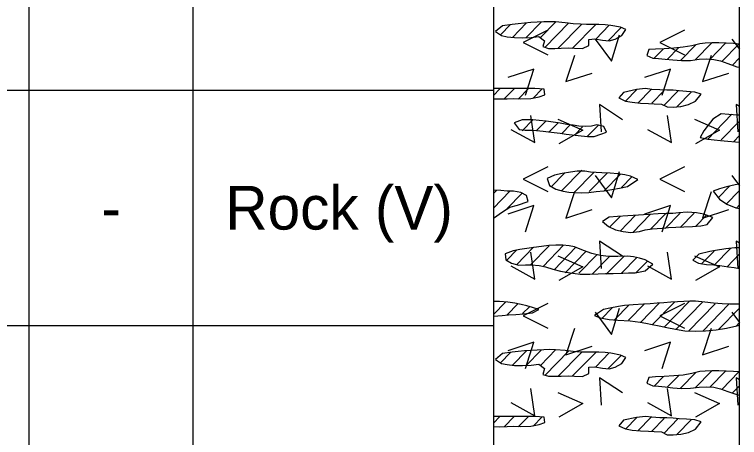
# Model space of a CAD drawing. Extents: x 0 to 0.83, y -0.65 to 1.27.
# Drawn here: x 0.7228 to 0.8333, y 0.0905 to 0.155 of the extents above; entities that cross this region are included whole.
import ezdxf

# ---------------------------------------------------------------- set-up
doc = ezdxf.new("R2010")
doc.units = 0

msp = doc.modelspace()

# ---------------------------------------------------------------- linework, layer by layer
for points in [[(0, 0), (0.83333, 0), (0.83333, 1.275), (0, 1.275)], [(0, 0), (0.83333, 0), (0.83333, 1.275), (0, 1.275)], [(0, 0), (0.83333, 0), (0.83333, 1.275), (0, 1.275)], [(0, 0), (0.83333, 0), (0.83333, 1.275), (0, 1.275)], [(0, 0), (0.83333, 0), (0.83333, 1.275), (0, 1.275)], [(0.79708, 0.15181), (0.79794, 0.15163), (0.79904, 0.15152), (0.80028, 0.15149), (0.80156, 0.15154), (0.80274, 0.1517), (0.80361, 0.15103), (0.80338, 0.15014), (0.80422, 0.14987), (0.80517, 0.14985), (0.80613, 0.1499), (0.8072, 0.14993), (0.80818, 0.1499), (0.80939, 0.14983), (0.81037, 0.1503), (0.81038, 0.15124), (0.8113, 0.15131), (0.81244, 0.15112), (0.81346, 0.15101), (0.81438, 0.15127), (0.81539, 0.15181), (0.81601, 0.15272), (0.81517, 0.1531), (0.81374, 0.15337), (0.81285, 0.15346), (0.81187, 0.15352), (0.81, 0.15352), (0.8091, 0.15354), (0.808, 0.15362), (0.80678, 0.15377), (0.8053, 0.1539), (0.80443, 0.15392), (0.80349, 0.1539), (0.80251, 0.15386), (0.80152, 0.1538), (0.80054, 0.15372), (0.79959, 0.15363), (0.7987, 0.15353), (0.79722, 0.15331), (0.79614, 0.15243)], [(0.83241, 0.15059), (0.83129, 0.15066), (0.83017, 0.15069), (0.8291, 0.1507), (0.82811, 0.15066), (0.82728, 0.15057), (0.82608, 0.15027), (0.82476, 0.15004), (0.8233, 0.14991), (0.82183, 0.14982), (0.82051, 0.14976), (0.81951, 0.14967), (0.81922, 0.1488), (0.82013, 0.14838), (0.82097, 0.14833), (0.822, 0.14823), (0.82318, 0.1481), (0.82448, 0.14801), (0.82584, 0.14804), (0.82719, 0.1482), (0.82836, 0.14827), (0.8294, 0.14819), (0.83043, 0.14795), (0.83156, 0.14756), (0.83291, 0.14707), (0.83333, 0.147), (0.83333, 0.15052)], [(0.79583, 0.14218), (0.79676, 0.14217), (0.79792, 0.14219), (0.79882, 0.14223), (0.79992, 0.14218), (0.80151, 0.14223), (0.80282, 0.14248), (0.80367, 0.1428), (0.80354, 0.14364), (0.80216, 0.14373), (0.79583, 0.14373)], [(0.81822, 0.14153), (0.81944, 0.14148), (0.82033, 0.14143), (0.82145, 0.14137), (0.82229, 0.14095), (0.82324, 0.14091), (0.82438, 0.14101), (0.82555, 0.1413), (0.82662, 0.14181), (0.82749, 0.1429), (0.82651, 0.14321), (0.82524, 0.14331), (0.82413, 0.14337), (0.82324, 0.14348), (0.82226, 0.1435), (0.82121, 0.14352), (0.81995, 0.14361), (0.81902, 0.14373), (0.81761, 0.14359), (0.81566, 0.14314), (0.81496, 0.14231), (0.81598, 0.14182), (0.81695, 0.14164)], [(0.83305, 0.13968), (0.83171, 0.13979), (0.83054, 0.13989), (0.82925, 0.13907), (0.82857, 0.13816), (0.82792, 0.13727), (0.82735, 0.13625), (0.82858, 0.13602), (0.82945, 0.13592), (0.83045, 0.13582), (0.83155, 0.13573), (0.83272, 0.13563), (0.83333, 0.13558), (0.83333, 0.13967)], [(0.80066, 0.13738), (0.80188, 0.13737), (0.80339, 0.13724), (0.80423, 0.13715), (0.8051, 0.13704), (0.806, 0.13692), (0.80692, 0.1368), (0.80784, 0.13668), (0.80875, 0.13657), (0.81014, 0.13643), (0.81119, 0.13644), (0.81222, 0.13678), (0.81308, 0.13707), (0.81267, 0.13797), (0.8116, 0.13822), (0.81075, 0.13802), (0.80989, 0.13794), (0.80885, 0.13802), (0.80799, 0.13813), (0.80703, 0.13827), (0.806, 0.13844), (0.80492, 0.1386), (0.80384, 0.13876), (0.8028, 0.13889), (0.80182, 0.13898), (0.8002, 0.13899), (0.79901, 0.13852), (0.79974, 0.13748)], [(0.81233, 0.13087), (0.81063, 0.13099), (0.80977, 0.13112), (0.8086, 0.13113), (0.80755, 0.13099), (0.80632, 0.13079), (0.80513, 0.13054), (0.80403, 0.13002), (0.80436, 0.12896), (0.80536, 0.1284), (0.80647, 0.1281), (0.8073, 0.12795), (0.80824, 0.12787), (0.80926, 0.12786), (0.81035, 0.12791), (0.81149, 0.12802), (0.81267, 0.12816), (0.81386, 0.12835), (0.81506, 0.12856), (0.81625, 0.12879), (0.81783, 0.12987), (0.81673, 0.13037), (0.81585, 0.13058), (0.8148, 0.13073), (0.81361, 0.13084)], [(0.79583, 0.12396), (0.79719, 0.12495), (0.79831, 0.12565), (0.79951, 0.12593), (0.80111, 0.12653), (0.80086, 0.12741), (0.80002, 0.12789), (0.79889, 0.12808), (0.79791, 0.12811), (0.79694, 0.12817), (0.79583, 0.12825)], [(0.83265, 0.12906), (0.83136, 0.12875), (0.83028, 0.12847), (0.82934, 0.12808), (0.83026, 0.12688), (0.83142, 0.12612), (0.83279, 0.12554), (0.83333, 0.12544), (0.83333, 0.12915)], [(0.82537, 0.12491), (0.82408, 0.12476), (0.82319, 0.1247), (0.82214, 0.12467), (0.82091, 0.12464), (0.81947, 0.12455), (0.81792, 0.12443), (0.81632, 0.12431), (0.81475, 0.12421), (0.81348, 0.12411), (0.81247, 0.12347), (0.81337, 0.12271), (0.81444, 0.12221), (0.81561, 0.12192), (0.81675, 0.12181), (0.81807, 0.12193), (0.81896, 0.1222), (0.82003, 0.12235), (0.82157, 0.12247), (0.82253, 0.12253), (0.82362, 0.12258), (0.82483, 0.12265), (0.82618, 0.12271), (0.82745, 0.12282), (0.82842, 0.123), (0.82927, 0.12405), (0.82791, 0.12457), (0.82679, 0.12477)], [(0.79885, 0.119), (0.79763, 0.11854), (0.79773, 0.11764), (0.79859, 0.11712), (0.7997, 0.11682), (0.80074, 0.11683), (0.80165, 0.11684), (0.80281, 0.11676), (0.80377, 0.11655), (0.80486, 0.1162), (0.80606, 0.11591), (0.80751, 0.11563), (0.80905, 0.11545), (0.81052, 0.11542), (0.81177, 0.11547), (0.81289, 0.11552), (0.81408, 0.11555), (0.81553, 0.11559), (0.81642, 0.11562), (0.81745, 0.11565), (0.81897, 0.11592), (0.82011, 0.11696), (0.81896, 0.11763), (0.8181, 0.11789), (0.81717, 0.11809), (0.81626, 0.1182), (0.81479, 0.11814), (0.81343, 0.11814), (0.8121, 0.11829), (0.8108, 0.11859), (0.80953, 0.11905), (0.8082, 0.1196), (0.80736, 0.11976), (0.8064, 0.11984), (0.80536, 0.11984), (0.80427, 0.11978), (0.80314, 0.11967), (0.80201, 0.11952), (0.8009, 0.11935), (0.79984, 0.11918)], [(0.83263, 0.11944), (0.83126, 0.11931), (0.82969, 0.11904), (0.82883, 0.11887), (0.82712, 0.11846), (0.82623, 0.11759), (0.82708, 0.1171), (0.82831, 0.11691), (0.82941, 0.11684), (0.83033, 0.11675), (0.83165, 0.11657), (0.83253, 0.11643), (0.83333, 0.11629), (0.83333, 0.11944)], [(0.79583, 0.10904), (0.79715, 0.10915), (0.79814, 0.10922), (0.79922, 0.1093), (0.80039, 0.10939), (0.80179, 0.10951), (0.80275, 0.11002), (0.80179, 0.11036), (0.80091, 0.11058), (0.80003, 0.1108), (0.79909, 0.11101), (0.79803, 0.11117), (0.79677, 0.11127), (0.79583, 0.11125)], [(0.82816, 0.10679), (0.82978, 0.10696), (0.83137, 0.10721), (0.8329, 0.10753), (0.83333, 0.10763), (0.83333, 0.11087), (0.83295, 0.11084), (0.83188, 0.11086), (0.83071, 0.11091), (0.82938, 0.11101), (0.82807, 0.11118), (0.82662, 0.1113), (0.82576, 0.1113), (0.82484, 0.11128), (0.82387, 0.11123), (0.82286, 0.11116), (0.82182, 0.11108), (0.82077, 0.11099), (0.81973, 0.11091), (0.81872, 0.11084), (0.81715, 0.11074), (0.81579, 0.11065), (0.81491, 0.11052), (0.81357, 0.11024), (0.8126, 0.11003), (0.81121, 0.10911), (0.8121, 0.10875), (0.81345, 0.1085), (0.81479, 0.10841), (0.81668, 0.10831), (0.81818, 0.10811), (0.81905, 0.10796), (0.82, 0.10778), (0.82107, 0.10757), (0.82225, 0.10732), (0.82357, 0.10703), (0.82501, 0.1068), (0.82656, 0.10673)], [(0.79708, 0.10181), (0.79794, 0.10163), (0.79904, 0.10152), (0.80028, 0.10149), (0.80156, 0.10154), (0.80274, 0.1017), (0.80361, 0.10103), (0.80338, 0.10014), (0.80422, 0.09987), (0.80517, 0.09985), (0.80613, 0.0999), (0.8072, 0.09993), (0.80818, 0.0999), (0.80939, 0.09983), (0.81037, 0.1003), (0.81038, 0.10124), (0.8113, 0.10131), (0.81244, 0.10112), (0.81346, 0.10101), (0.81438, 0.10127), (0.81539, 0.10181), (0.81601, 0.10272), (0.81517, 0.1031), (0.81374, 0.10337), (0.81285, 0.10346), (0.81187, 0.10352), (0.81, 0.10352), (0.8091, 0.10354), (0.808, 0.10362), (0.80678, 0.10377), (0.8053, 0.1039), (0.80443, 0.10392), (0.80349, 0.1039), (0.80251, 0.10386), (0.80152, 0.1038), (0.80054, 0.10372), (0.79959, 0.10363), (0.7987, 0.10353), (0.79722, 0.10331), (0.79614, 0.10243)], [(0.83241, 0.10059), (0.83129, 0.10066), (0.83017, 0.10069), (0.8291, 0.1007), (0.82811, 0.10066), (0.82728, 0.10057), (0.82608, 0.10027), (0.82476, 0.10004), (0.8233, 0.09991), (0.82183, 0.09982), (0.82051, 0.09976), (0.81951, 0.09967), (0.81922, 0.0988), (0.82013, 0.09838), (0.82097, 0.09833), (0.822, 0.09823), (0.82318, 0.0981), (0.82448, 0.09801), (0.82584, 0.09804), (0.82719, 0.0982), (0.82836, 0.09827), (0.8294, 0.09819), (0.83043, 0.09795), (0.83156, 0.09756), (0.83291, 0.09707), (0.83333, 0.097), (0.83333, 0.10052)], [(0.79583, 0.09218), (0.79676, 0.09217), (0.79792, 0.09219), (0.79882, 0.09223), (0.79992, 0.09218), (0.80151, 0.09223), (0.80282, 0.09248), (0.80367, 0.0928), (0.80354, 0.09364), (0.80216, 0.09373), (0.79583, 0.09373)], [(0.81822, 0.09153), (0.81944, 0.09148), (0.82033, 0.09143), (0.82145, 0.09137), (0.82229, 0.09095), (0.82324, 0.09091), (0.82438, 0.09101), (0.82555, 0.0913), (0.82662, 0.09181), (0.82749, 0.0929), (0.82651, 0.09321), (0.82524, 0.09331), (0.82413, 0.09337), (0.82324, 0.09348), (0.82226, 0.0935), (0.82121, 0.09352), (0.81995, 0.09361), (0.81902, 0.09373), (0.81761, 0.09359), (0.81566, 0.09314), (0.81496, 0.09231), (0.81598, 0.09182), (0.81695, 0.09164)]]:
    msp.add_lwpolyline(points, close=True)
for points in [[(0.725, 1.22083), (0.725, -0.64575)], [(0.75, 1.22083), (0.75, -0.64575)], [(0.75, 1.22083), (0.75, -0.64575)], [(0.79583, 1.22083), (0.79583, -0.64575)], [(0.725, 1.20833), (0.725, -0.64575)], [(0.83333, -0.64575), (0.83333, 1.13365)], [(0.79871, 0.15155), (0.80085, 0.15374)], [(0.80083, 0.15151), (0.80311, 0.15385)], [(0.80534, 0.15392), (0.80299, 0.15151)], [(0.80367, 0.15), (0.80732, 0.15374)], [(0.79844, 0.15349), (0.79691, 0.15192)], [(0.80412, 0.15263), (0.80038, 0.15076), (0.80412, 0.14888)], [(0.80571, 0.14988), (0.80924, 0.15349)], [(0.81142, 0.15351), (0.80785, 0.14986)], [(0.81141, 0.15129), (0.81348, 0.15341)], [(0.81528, 0.15305), (0.81331, 0.15103)], [(0.82496, 0.15263), (0.82121, 0.15076), (0.82496, 0.14888)], [(0.81134, 0.15129), (0.81384, 0.14792), (0.81503, 0.15192)], [(0.82433, 0.14802), (0.82666, 0.15041)], [(0.82909, 0.1507), (0.82656, 0.1481)], [(0.82885, 0.14823), (0.83122, 0.15066)], [(0.83325, 0.15052), (0.83065, 0.14786)], [(0.83217, 0.15129), (0.83333, 0.14973)], [(0.82035, 0.14837), (0.82176, 0.14982)], [(0.82233, 0.14819), (0.82408, 0.14998)], [(0.80818, 0.1488), (0.80687, 0.1448), (0.81087, 0.14611)], [(0.82901, 0.1488), (0.8277, 0.1448), (0.8317, 0.14611)], [(0.83333, 0.1484), (0.83227, 0.14731)], [(0.80069, 0.14272), (0.802, 0.14672), (0.798, 0.14541)], [(0.82152, 0.14272), (0.82284, 0.14672), (0.81884, 0.14541)], [(0.79583, 0.1427), (0.79681, 0.1437)], [(0.79898, 0.14372), (0.79747, 0.14217)], [(0.80116, 0.14373), (0.79959, 0.14213)], [(0.80328, 0.14369), (0.80188, 0.14226)], [(0.70417, 0.1435), (0.725, 0.1435)], [(0.725, 0.1435), (0.75, 0.1435)], [(0.75, 0.1435), (0.79583, 0.1435)], [(0.8177, 0.14359), (0.81596, 0.14181)], [(0.81988, 0.14361), (0.81785, 0.14153)], [(0.82185, 0.14342), (0.81997, 0.14149)], [(0.824, 0.14341), (0.82178, 0.14113)], [(0.82601, 0.14325), (0.82378, 0.14097)], [(0.81551, 0.13899), (0.81201, 0.14131), (0.81226, 0.13712)], [(0.83333, 0.14098), (0.83284, 0.14131), (0.83309, 0.13712)], [(0.79847, 0.13751), (0.80215, 0.13551), (0.80153, 0.13964)], [(0.8193, 0.13751), (0.82299, 0.13551), (0.82236, 0.13964)], [(0.83217, 0.13981), (0.82844, 0.13599)], [(0.80188, 0.13903), (0.8002, 0.13731)], [(0.8038, 0.13879), (0.80237, 0.13733)], [(0.80575, 0.13857), (0.80429, 0.13708)], [(0.80562, 0.13906), (0.80946, 0.13737), (0.80581, 0.13531)], [(0.80758, 0.13824), (0.80627, 0.13689)], [(0.81188, 0.13821), (0.81016, 0.13646)], [(0.82645, 0.13906), (0.83029, 0.13737), (0.82664, 0.13531)], [(0.83333, 0.13879), (0.83052, 0.13591)], [(0.80941, 0.1379), (0.80816, 0.13662)], [(0.83333, 0.13657), (0.83245, 0.13567)], [(0.80412, 0.1318), (0.80038, 0.12992), (0.80412, 0.12805)], [(0.82496, 0.1318), (0.82121, 0.12992), (0.82496, 0.12805)], [(0.80465, 0.12875), (0.80667, 0.13083)], [(0.80626, 0.12819), (0.80928, 0.13128)], [(0.80809, 0.12785), (0.81111, 0.13095)], [(0.81041, 0.12802), (0.81318, 0.13085)], [(0.81134, 0.13046), (0.81384, 0.12708), (0.81503, 0.13108)], [(0.81264, 0.1281), (0.81518, 0.1307)], [(0.83217, 0.13046), (0.83333, 0.1289)], [(0.81536, 0.12867), (0.81699, 0.13033)], [(0.7963, 0.12821), (0.79583, 0.12773)], [(0.8301, 0.12709), (0.83184, 0.12888)], [(0.83131, 0.12612), (0.83333, 0.12819)], [(0.79834, 0.12808), (0.79583, 0.12551)], [(0.79786, 0.12538), (0.80023, 0.12781)], [(0.80818, 0.12797), (0.80687, 0.12397), (0.81087, 0.12528)], [(0.82901, 0.12797), (0.8277, 0.12397), (0.8317, 0.12528)], [(0.83285, 0.12549), (0.83333, 0.12598)], [(0.80069, 0.12189), (0.802, 0.12589), (0.798, 0.12457)], [(0.82152, 0.12189), (0.82284, 0.12589), (0.81884, 0.12457)], [(0.81519, 0.12428), (0.81354, 0.12258)], [(0.81514, 0.12201), (0.81748, 0.12441)], [(0.81709, 0.1218), (0.81974, 0.12451)], [(0.8197, 0.12225), (0.82203, 0.12465)], [(0.82202, 0.12242), (0.8243, 0.12475)], [(0.82431, 0.12255), (0.82644, 0.12474)], [(0.82663, 0.12271), (0.82834, 0.12447)], [(0.81551, 0.11816), (0.81201, 0.12047), (0.81226, 0.11628)], [(0.83333, 0.12015), (0.83284, 0.12047), (0.83309, 0.11628)], [(0.79933, 0.11687), (0.80195, 0.11956)], [(0.80142, 0.1168), (0.8043, 0.11975)], [(0.80653, 0.11983), (0.8034, 0.11661)], [(0.80506, 0.1161), (0.8084, 0.11953)], [(0.83203, 0.11939), (0.82949, 0.11679)], [(0.79938, 0.11913), (0.79786, 0.11758)], [(0.79847, 0.11668), (0.80215, 0.11468), (0.80153, 0.1188)], [(0.80997, 0.11893), (0.80675, 0.11562)], [(0.81164, 0.11842), (0.80884, 0.11556)], [(0.81303, 0.11542), (0.81579, 0.11825)], [(0.8193, 0.11668), (0.82299, 0.11468), (0.82236, 0.1188)], [(0.82751, 0.11698), (0.82945, 0.11896)], [(0.83138, 0.11652), (0.83333, 0.11852)], [(0.80562, 0.11822), (0.80946, 0.11654), (0.80581, 0.11448)], [(0.81353, 0.11814), (0.81094, 0.11549)], [(0.81534, 0.11558), (0.81768, 0.11797)], [(0.8176, 0.11568), (0.81934, 0.11747)], [(0.82645, 0.11822), (0.83029, 0.11654), (0.82664, 0.11448)], [(0.83333, 0.1163), (0.83333, 0.11631)], [(0.79765, 0.11115), (0.79583, 0.10928)], [(0.7996, 0.11094), (0.79786, 0.10916)], [(0.80412, 0.11096), (0.80038, 0.10909), (0.80412, 0.10721)], [(0.8143, 0.10848), (0.8165, 0.11073)], [(0.8164, 0.10841), (0.81879, 0.11086)], [(0.81829, 0.10813), (0.82114, 0.11105)], [(0.82004, 0.10771), (0.82346, 0.11122)], [(0.82496, 0.11096), (0.82121, 0.10909), (0.82496, 0.10721)], [(0.82569, 0.1113), (0.82184, 0.10735)], [(0.82775, 0.11119), (0.8237, 0.10705)], [(0.82964, 0.11092), (0.82557, 0.10674)], [(0.83173, 0.11085), (0.82774, 0.10676)], [(0.8013, 0.11046), (0.80027, 0.10941)], [(0.81134, 0.10962), (0.81384, 0.10625), (0.81503, 0.11025)], [(0.81392, 0.1103), (0.81235, 0.10869)], [(0.83333, 0.11027), (0.83012, 0.10698)], [(0.83217, 0.10962), (0.83333, 0.10806)], [(0.70417, 0.10762), (0.725, 0.10762)], [(0.725, 0.10762), (0.75, 0.10762)], [(0.75, 0.10762), (0.79583, 0.10762)], [(0.83281, 0.10752), (0.83333, 0.10806)], [(0.80818, 0.10713), (0.80687, 0.10313), (0.81087, 0.10445)], [(0.82901, 0.10713), (0.8277, 0.10313), (0.8317, 0.10445)], [(0.80069, 0.10105), (0.802, 0.10505), (0.798, 0.10374)], [(0.82152, 0.10105), (0.82284, 0.10505), (0.81884, 0.10374)], [(0.80534, 0.10393), (0.80299, 0.10151)], [(0.79844, 0.10349), (0.79691, 0.10192)], [(0.79871, 0.10155), (0.80085, 0.10375)], [(0.80083, 0.10151), (0.80311, 0.10385)], [(0.80367, 0.1), (0.80732, 0.10374)], [(0.80571, 0.09988), (0.80924, 0.10349)], [(0.81142, 0.10351), (0.80785, 0.09986)], [(0.81141, 0.10129), (0.81348, 0.10341)], [(0.81528, 0.10305), (0.81331, 0.10103)], [(0.82909, 0.1007), (0.82656, 0.0981)], [(0.82885, 0.09823), (0.83122, 0.10066)], [(0.81551, 0.09733), (0.81201, 0.09964), (0.81226, 0.09545)], [(0.82035, 0.09837), (0.82176, 0.09982)], [(0.82233, 0.09819), (0.82408, 0.09998)], [(0.82433, 0.09802), (0.82666, 0.10041)], [(0.83325, 0.10052), (0.83065, 0.09786)], [(0.83333, 0.09932), (0.83284, 0.09964), (0.83309, 0.09545)], [(0.83333, 0.0984), (0.83227, 0.09731)], [(0.79847, 0.09584), (0.80215, 0.09384), (0.80153, 0.09797)], [(0.80562, 0.09739), (0.80946, 0.09571), (0.80581, 0.09364)], [(0.8193, 0.09584), (0.82299, 0.09384), (0.82236, 0.09797)], [(0.82645, 0.09739), (0.83029, 0.09571), (0.82664, 0.09364)], [(0.79583, 0.0927), (0.79681, 0.0937)], [(0.79898, 0.09372), (0.79747, 0.09217)], [(0.80116, 0.09373), (0.79959, 0.09213)], [(0.80328, 0.09369), (0.80188, 0.09226)], [(0.8177, 0.09359), (0.81596, 0.09181)], [(0.81988, 0.09361), (0.81785, 0.09153)], [(0.82185, 0.09342), (0.81997, 0.09149)], [(0.824, 0.09341), (0.82178, 0.09113)], [(0.82601, 0.09325), (0.82378, 0.09097)]]:
    msp.add_lwpolyline(points)

# ---------------------------------------------------------------- texts
for s, height, p in [('Rock (V)', 0.006667, (0.75497, 0.12223)), ('-', 0.00667, (0.73609, 0.12223))]:
    msp.add_text(s, height=height).set_placement(p)

doc.saveas('drawing.dxf')
